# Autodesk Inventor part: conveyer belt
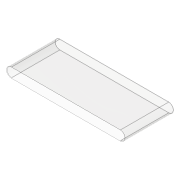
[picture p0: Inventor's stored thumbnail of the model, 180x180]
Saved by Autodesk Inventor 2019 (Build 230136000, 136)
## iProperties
Created: 2019-10
Part Number: conveyer belt
Material: PMMA Plastic
Document SubType Name: Modeling
Designer: hp
Density: 1.188 g/cm^3
Appearance: Polycarbonate - Clear
Surface Area: 2577.92 cm^2
Author: hp
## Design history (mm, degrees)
sketch "Sketch1"
  geometry: L1 (-270.086, 35.093)-(169.914, 35.093); L2 (-252.086, 17.093)-(151.914, 17.093); L3 (151.914, 53.093)-(-252.086, 53.093); A1 r 18 centre (-252.086, 35.093) between (-252.086, 53.093) and (-252.086, 17.093); A2 r 18 centre (151.914, 35.093) between (151.914, 17.093) and (151.914, 53.093); 2 further points
  constraints: 8 end point, 6 point on circle, 4 tangent, 2 centre point, 2 point on line, 1 horizontal, 1 midpoint, 1 parallel
  dimensions: "d0" = 440 distance of L1.start L1.end; "d1" = 36 diameter of A2
extrude "Extrusion1" new body sketch "Sketch1" distance "d2" = 180; taper "d3" = 0 deg
shell "Shell1" dims "d4" = 1.5
delete_face "Delete Face1"
delete_face "Delete Face2"
body "Solid1"
